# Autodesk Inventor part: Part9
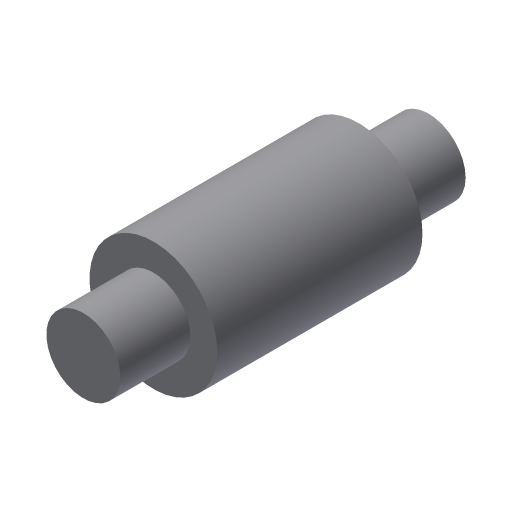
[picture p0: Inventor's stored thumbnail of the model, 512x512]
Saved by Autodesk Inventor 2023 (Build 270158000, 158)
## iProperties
Created: 2002-01
Part Number: Part9
Document SubType Name: Modeling
Designer: ***
Density: 1 g/cm^3
Material: Generic
Appearance: Default
Control State: 0
Master: False
Checked Out: False
Shininess: 77.0
Length Units: 11269
Angle Units: 11279
Time Units: 11290
Mass Units: 11283
Length Display Precision: 3
Angle Display Precision: 2
Density: 0.0
Volumn: 0.0
Area: 0.0
PropertySet Name: Model Information
Author: ***
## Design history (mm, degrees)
sketch "Sketch1"
  geometry: L1 (0.279, 23.245)-(5.19, 23.245); L2 (5.19, 23.245)-(5.19, 13.947); L3 (5.19, 13.947)-(8.761, 13.947); L4 (8.761, 13.947)-(8.761, -13.295); L5 (8.761, -13.295)-(5.19, -13.295); L6 (5.19, -13.295)-(5.19, -22.592); L7 (5.19, -22.592)-(0.279, -22.592); L8 (0.279, -22.592)-(0.279, 23.245)
  constraints: 16 end point, 5 parallel, 2 equal length, 1 collinear, 1 horizontal, 1 perpendicular
revolve "Revolution1" sketch "Sketch1" stored, may be unused: angle "d0" = 90 deg
body "Solid1"
